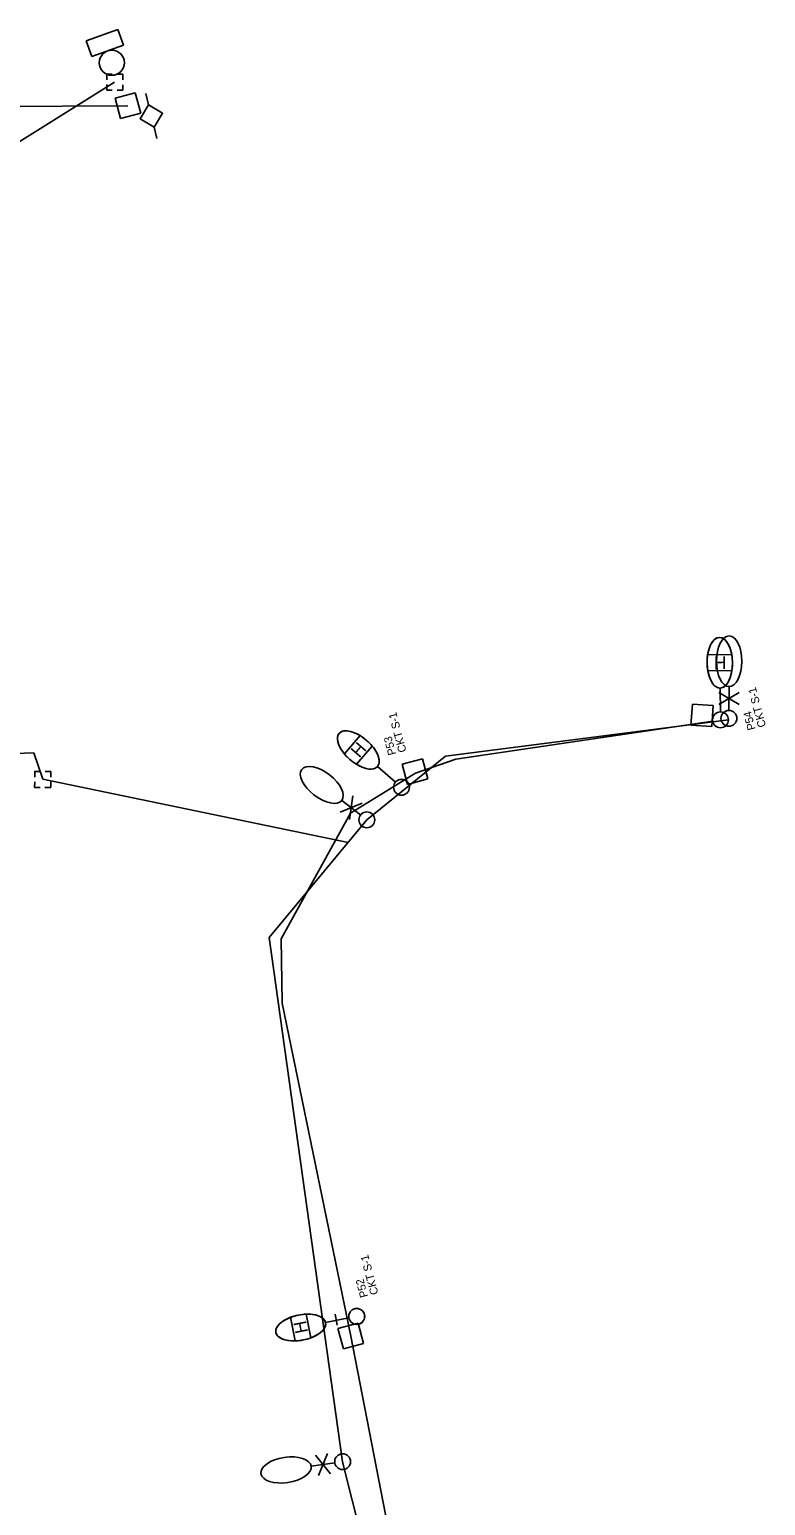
# Model space of a CAD drawing. Extents: x 925407 to 931638, y 609358 to 637063.
# Drawn here: x 930754.2 to 930983.9, y 629066.9 to 629527.9 of the extents above; entities that cross this region are included whole.
import ezdxf

# ---------------------------------------------------------------- set-up
doc = ezdxf.new("R2010")
doc.units = 0
for name, color, linetype in [('ActivePointCell_dp', 7, 'Continuous'), ('Conduit', 7, 'Continuous'), ('ConduitDB', 7, 'Continuous'), ('ConduitOT', 7, 'Continuous'), ('LiteCond_ep', 7, 'Continuous'), ('LoadCenter_ep', 7, 'Continuous'), ('Miscellaneous2', 7, 'Continuous'), ('PoleElec_ep', 7, 'Continuous'), ('PoleLight', 7, 'Continuous'), ('PoleLight_ep', 7, 'Continuous'), ('PullBox', 7, 'Continuous'), ('TextLabel', 7, 'Continuous')]:
    doc.layers.add(name, color=color, linetype=linetype)

msp = doc.modelspace()

# ---------------------------------------------------------------- linework, layer by layer
at = {"layer": 'ActivePointCell_dp'}
msp.add_line((930850.28, 629123.17), (930849.59, 629126.63), dxfattribs=at)
at = {"layer": 'Conduit'}
for p, q in [((930721.08, 629474.1), (930780.76, 629511.4)), ((930519.05, 629293.47), (930755.53, 629302.01)), ((930755.53, 629302.01), (930758.36, 629293.72))]:
    msp.add_line(p, q, dxfattribs=at)
at = {"layer": 'ConduitDB'}
msp.add_line((930784.91, 629504.06), (930708.05, 629503.58), dxfattribs=at)
at = {"layer": 'ConduitOT'}
for p, q in [((930887.29, 629299.97), (930967.45, 629311.87)), ((930874.71, 629295.56), (930887.29, 629299.97)), ((930854.38, 629283.14), (930874.71, 629295.56)), ((930832.79, 629243.9), (930854.38, 629283.14)), ((930833.02, 629223.8), (930832.79, 629243.9)), ((930854.5, 629119.82), (930833.02, 629223.8)), ((930876.98, 629003.85), (930854.5, 629119.82))]:
    msp.add_line(p, q, dxfattribs=at)
at = {"layer": 'LiteCond_ep'}
for p, q in [((930758.36, 629293.72), (930853.67, 629274)), ((930897.17, 628900.19), (930851.93, 629080.57))]:
    msp.add_line(p, q, dxfattribs=at)
for points in [[(930859.51, 629281.03), (930884.04, 629300.91), (930972.37, 629312.31)], [(930851.93, 629080.57), (930828.98, 629244.28), (930859.51, 629281.03)]]:
    msp.add_lwpolyline(points, dxfattribs=at)
at = {"layer": 'LoadCenter_ep'}
for p, q in [((930771.88, 629524.32), (930781.72, 629527.87)), ((930781.72, 629527.87), (930783.49, 629522.95)), ((930773.65, 629519.4), (930771.88, 629524.32)), ((930783.49, 629522.95), (930773.65, 629519.4))]:
    msp.add_line(p, q, dxfattribs=at)
msp.add_circle((930779.9, 629517.49), 3.92, dxfattribs=at)
at = {"layer": 'Miscellaneous2'}
for p, q in [((930973.39, 629332.65), (930965.88, 629332.55)), ((930973.39, 629332.65), (930973.39, 629332.65)), ((930965.94, 629327.55), (930973.46, 629327.65)), ((930973.46, 629327.65), (930973.46, 629327.65)), ((930857.39, 629307.33), (930852.48, 629301.64)), ((930857.39, 629307.33), (930857.39, 629307.33)), ((930856.26, 629298.38), (930861.17, 629304.07)), ((930861.17, 629304.07), (930861.17, 629304.07)), ((930835.68, 629125.66), (930835.68, 629125.66)), ((930835.68, 629125.66), (930837.14, 629118.29)), ((930842.05, 629119.26), (930840.58, 629126.63)), ((930840.58, 629126.63), (930840.58, 629126.63))]:
    msp.add_line(p, q, dxfattribs=at)
for centre, major_axis, start_param, end_param in [((930969.67, 629330.1), (0.1, -7.92), 4.391271, 5.033538), ((930969.67, 629330.1), (0.1, -7.92), 4.391241, 4.391271), ((930969.67, 629330.1), (0.1, -7.92), 1.249648, 1.891946), ((930856.82, 629302.86), (5.99, -5.18), 1.249648, 1.891946), ((930856.82, 629302.86), (5.99, -5.18), 4.391241, 4.391271), ((930856.82, 629302.86), (5.99, -5.18), 4.391271, 5.033538), ((930838.86, 629122.46), (7.77, 1.55), 1.249648, 1.891946), ((930838.86, 629122.46), (7.77, 1.55), 4.391271, 5.033538), ((930838.86, 629122.46), (7.77, 1.55), 4.391241, 4.391271)]:
    msp.add_ellipse(centre, major_axis=major_axis, ratio=0.5, start_param=start_param, end_param=end_param, dxfattribs=at)
at = {"layer": 'PoleElec_ep'}
for p, q in [((930790.51, 629507.92), (930791.37, 629504.38)), ((930793.93, 629493.82), (930793.07, 629497.36))]:
    msp.add_line(p, q, dxfattribs=at)
msp.add_lwpolyline([(930791.37, 629504.38), (930788.71, 629500.02), (930793.07, 629497.36), (930795.74, 629501.72), (930791.37, 629504.38)], dxfattribs=at)
at = {"layer": 'PoleLight'}
for p, q in [((930965.88, 629332.55), (930973.39, 629332.65)), ((930973.46, 629327.65), (930965.94, 629327.55)), ((930969.86, 629314.76), (930969.77, 629322.18)), ((930852.48, 629301.64), (930857.39, 629307.33)), ((930861.17, 629304.07), (930856.26, 629298.38)), ((930868.44, 629292.83), (930862.82, 629297.68)), ((930837.14, 629118.29), (930835.68, 629125.66)), ((930840.58, 629126.63), (930842.05, 629119.26)), ((930853.91, 629125.46), (930846.63, 629124.01))]:
    msp.add_line(p, q, dxfattribs=at)
for centre, radius in [((930969.89, 629312.28), 2.48), ((930969.89, 629312.28), 2.47), ((930870.31, 629291.21), 2.48), ((930870.31, 629291.21), 2.47), ((930856.34, 629125.94), 2.48), ((930856.34, 629125.94), 2.47)]:
    msp.add_circle(centre, radius, dxfattribs=at)
for centre, major_axis in [((930969.67, 629330.1), (0.1, -7.92)), ((930856.82, 629302.86), (5.99, -5.18)), ((930838.86, 629122.46), (7.77, 1.55))]:
    msp.add_ellipse(centre, major_axis=major_axis, ratio=0.5, dxfattribs=at)
for centre, major_axis, start_param, end_param in [((930969.67, 629330.1), (0.1, -7.92), 1.891945, 4.391241), ((930969.67, 629330.1), (0.1, -7.92), 5.033538, 6.283185), ((930969.67, 629330.1), (0.1, -7.92), 0, 0.847605), ((930969.67, 629330.1), (0.1, -7.92), 0.847605, 1.249648), ((930856.82, 629302.86), (5.99, -5.18), 1.891945, 4.391241), ((930856.82, 629302.86), (5.99, -5.18), 0.847605, 1.249648), ((930856.82, 629302.86), (5.99, -5.18), 0, 0.847605), ((930856.82, 629302.86), (5.99, -5.18), 5.033538, 6.283185), ((930838.86, 629122.46), (7.77, 1.55), 1.891945, 4.391241), ((930838.86, 629122.46), (7.77, 1.55), 0.847605, 1.249648), ((930838.86, 629122.46), (7.77, 1.55), 0, 0.847605), ((930838.86, 629122.46), (7.77, 1.55), 5.033538, 6.283185)]:
    msp.add_ellipse(centre, major_axis=major_axis, ratio=0.5, start_param=start_param, end_param=end_param, dxfattribs=at)
at = {"layer": 'PoleLight_ep'}
for p, q in [((930975.76, 629320.76), (930969.32, 629317.07)), ((930969.33, 629320.78), (930975.75, 629317.05)), ((930972.53, 629315.2), (930972.55, 629322.63)), ((930857.56, 629282.55), (930851.68, 629287.09)), ((930855.12, 629288.5), (930854.12, 629281.14)), ((930851.18, 629283.41), (930858.06, 629286.22)), ((930849.48, 629080.21), (930842.13, 629079.13)), ((930843.5, 629082.58), (930848.11, 629076.76)), ((930844.44, 629076.22), (930847.18, 629083.12))]:
    msp.add_line(p, q, dxfattribs=at)
for centre, radius in [((930972.52, 629312.73), 2.48), ((930859.51, 629281.03), 2.48), ((930851.93, 629080.57), 2.47)]:
    msp.add_circle(centre, radius, dxfattribs=at)
for centre, major_axis in [((930972.58, 629330.55), (0.03, 7.92)), ((930845.42, 629291.94), (-6.26, 4.85)), ((930834.3, 629077.98), (-7.84, -1.15))]:
    msp.add_ellipse(centre, major_axis=major_axis, ratio=0.5, dxfattribs=at)
at = {"layer": 'PullBox'}
for p, q in [((930780.9, 629506.39), (930787.23, 629508.07)), ((930787.23, 629508.07), (930788.92, 629501.74)), ((930782.59, 629500.06), (930780.9, 629506.39)), ((930788.92, 629501.74), (930782.59, 629500.06)), ((930960.65, 629310.63), (930961.11, 629317.16)), ((930961.11, 629317.16), (930967.64, 629316.7)), ((930967.64, 629316.7), (930967.18, 629310.17)), ((930967.18, 629310.17), (930960.65, 629310.63)), ((930870.51, 629298.45), (930876.84, 629300.13)), ((930872.2, 629292.12), (930870.51, 629298.45)), ((930876.84, 629300.13), (930878.52, 629293.8)), ((930878.52, 629293.8), (930872.2, 629292.12)), ((930850.49, 629122.15), (930856.82, 629123.83)), ((930852.17, 629115.82), (930850.49, 629122.15)), ((930856.82, 629123.83), (930858.5, 629117.5)), ((930858.5, 629117.5), (930852.17, 629115.82))]:
    msp.add_line(p, q, dxfattribs=at)
for points in [[(930780.01, 629513.92), (930778.34, 629513.93), (930778.32, 629512.17)], [(930783.32, 629512.13), (930783.34, 629513.89), (930781.57, 629513.9)], [(930778.31, 629510.67), (930778.29, 629508.94), (930779.97, 629508.92)], [(930781.52, 629508.91), (930783.29, 629508.89)], [(930783.29, 629508.89), (930783.31, 629510.63)], [(930757.53, 629296.15), (930755.85, 629296.17), (930755.84, 629294.4)], [(930760.84, 629294.36), (930760.85, 629296.12), (930759.08, 629296.14)], [(930755.82, 629292.9), (930755.81, 629291.17), (930757.48, 629291.15)], [(930760.81, 629291.12), (930760.82, 629292.86)], [(930759.03, 629291.14), (930760.81, 629291.12)]]:
    msp.add_lwpolyline(points, dxfattribs=at)

# ---------------------------------------------------------------- texts
at = {"layer": 'ActivePointCell_dp'}
for s, p in [('CKT S-1', (930984.13, 629310.26)), ('CKT S-1', (930871.91, 629302.44)), ('P54', (930980.89, 629309.4)), ('P53', (930868.67, 629301.58)), ('CKT S-1', (930863.14, 629133.04)), ('P52', (930859.9, 629132.19))]:
    msp.add_text(s, height=2.5, rotation=104.7826, dxfattribs=at).set_placement(p)
at = {"layer": 'TextLabel'}
for rotation, p in [(0.7135, (930967.87, 629328.08)), (49.189, (930857.14, 629300.16)), (101.261, (930841.18, 629121.06))]:
    msp.add_text('H', height=4, rotation=rotation, dxfattribs=at).set_placement(p)

doc.saveas('drawing.dxf')
